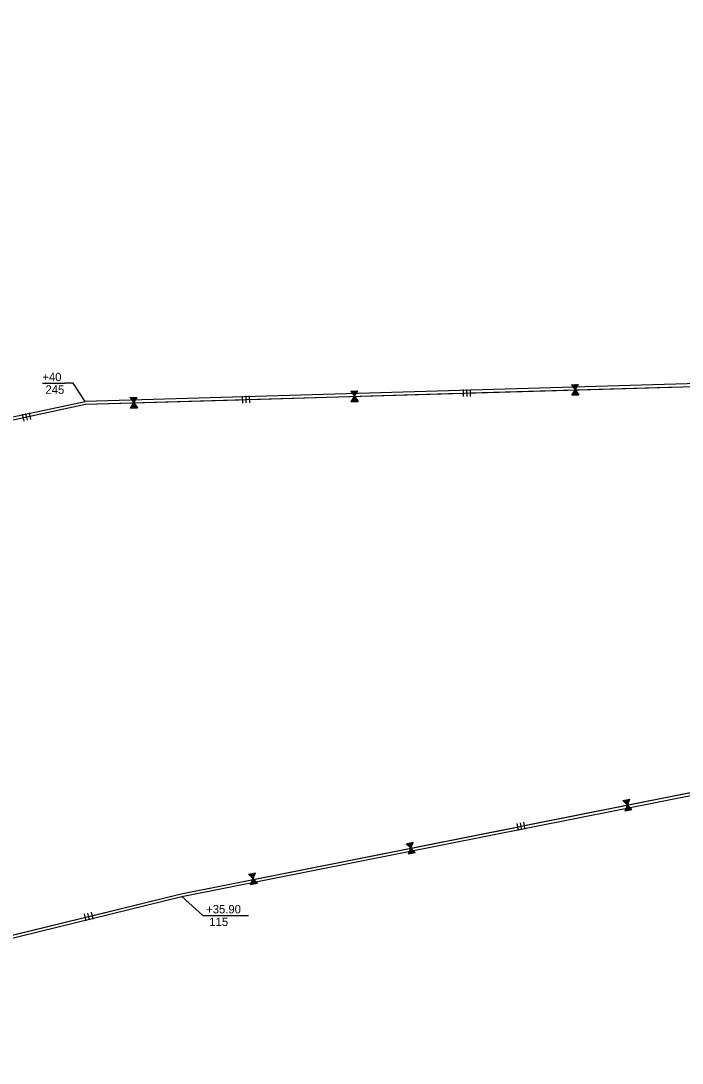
# Model space of a CAD drawing. Extents: x 979729 to 993523, y 1834148 to 1845433.
# Drawn here: x 985045 to 985517, y 1837649 to 1838393 of the extents above; entities that cross this region are included whole.
import ezdxf

# ---------------------------------------------------------------- set-up
doc = ezdxf.new("R2010")
doc.units = 0
for name, color, linetype in [('42', 7, 'Continuous'), ('51', 7, 'Continuous'), ('R_Draft', 7, 'Continuous')]:
    doc.layers.add(name, color=color, linetype=linetype)

msp = doc.modelspace()

# ---------------------------------------------------------------- linework, layer by layer
at = {"layer": '42'}
for p, q in [((985091.38, 1838119.28), (985811.99, 1838140.41)), ((985280.52, 1838128.58), (985283.13, 1838124.9)), ((985280.58, 1838128.52), (985280.62, 1838128.58)), ((985280.75, 1838128.32), (985280.92, 1838128.59)), ((985280.9, 1838128.08), (985281.22, 1838128.6)), ((985281.07, 1838127.88), (985281.52, 1838128.6)), ((985281.21, 1838127.64), (985281.82, 1838128.61)), ((985281.36, 1838127.4), (985282.12, 1838128.62)), ((985281.52, 1838127.2), (985282.42, 1838128.63)), ((985281.73, 1838127.05), (985282.63, 1838128.5)), ((985281.85, 1838126.78), (985283.02, 1838128.65)), ((985282.02, 1838126.58), (985283.32, 1838128.66)), ((985282.15, 1838126.32), (985283.62, 1838128.67)), ((985282.33, 1838126.14), (985283.92, 1838128.67)), ((985282.47, 1838125.87), (985284.22, 1838128.68)), ((985282.63, 1838125.67), (985284.52, 1838128.69)), ((985282.78, 1838125.43), (985284.82, 1838128.7)), ((985282.96, 1838125.25), (985285.12, 1838128.71)), ((985283.09, 1838124.99), (985285.42, 1838128.72)), ((985283.13, 1838124.9), (985285.52, 1838128.72)), ((985360.53, 1838129.67), (985360.67, 1838124.67)), ((985363.03, 1838129.74), (985363.17, 1838124.75)), ((985365.52, 1838129.82), (985365.67, 1838124.82)), ((985437.96, 1838133.19), (985440.57, 1838129.52)), ((985438.02, 1838133.14), (985438.05, 1838133.19)), ((985438.18, 1838132.94), (985438.35, 1838133.2)), ((985438.18, 1838125.69), (985440.57, 1838129.52)), ((985438.33, 1838132.7), (985438.65, 1838133.21)), ((985438.5, 1838132.49), (985438.95, 1838133.22)), ((985438.64, 1838132.26), (985439.25, 1838133.23)), ((985438.79, 1838132.02), (985439.55, 1838133.24)), ((985438.96, 1838131.81), (985439.85, 1838133.25)), ((985439.16, 1838131.67), (985440.06, 1838133.11)), ((985439.28, 1838131.4), (985440.45, 1838133.26)), ((985439.4, 1838127.56), (985440.67, 1838125.77)), ((985439.45, 1838131.19), (985440.75, 1838133.27)), ((985439.55, 1838127.78), (985440.97, 1838125.78)), ((985439.58, 1838130.93), (985441.05, 1838133.28)), ((985439.67, 1838128.05), (985441.27, 1838125.79)), ((985439.77, 1838130.75), (985441.35, 1838133.29)), ((985439.84, 1838128.24), (985441.57, 1838125.79)), ((985439.9, 1838130.49), (985441.65, 1838133.3)), ((985439.96, 1838128.5), (985441.87, 1838125.8)), ((985440.06, 1838130.29), (985441.95, 1838133.31)), ((985440.11, 1838128.72), (985442.17, 1838125.81)), ((985440.21, 1838130.05), (985442.25, 1838133.32)), ((985440.24, 1838128.96), (985442.47, 1838125.82)), ((985440.39, 1838129.87), (985442.55, 1838133.33)), ((985440.41, 1838129.15), (985442.77, 1838125.83)), ((985440.52, 1838129.61), (985442.85, 1838133.33)), ((985440.53, 1838129.42), (985443.07, 1838125.84)), ((985440.57, 1838129.52), (985442.95, 1838133.34)), ((985440.57, 1838129.52), (985443.17, 1838125.84)), ((985123.09, 1838123.96), (985125.7, 1838120.28)), ((985123.15, 1838123.91), (985123.19, 1838123.96)), ((985123.31, 1838116.46), (985125.7, 1838120.28)), ((985123.32, 1838123.7), (985123.49, 1838123.97)), ((985123.46, 1838123.47), (985123.79, 1838123.98)), ((985123.63, 1838123.26), (985124.09, 1838123.99)), ((985123.78, 1838123.02), (985124.39, 1838124)), ((985123.92, 1838122.79), (985124.69, 1838124.01)), ((985124.09, 1838122.58), (985124.99, 1838124.01)), ((985124.29, 1838122.43), (985125.2, 1838123.88)), ((985124.42, 1838122.16), (985125.59, 1838124.03)), ((985124.59, 1838121.96), (985125.89, 1838124.04)), ((985124.72, 1838121.7), (985126.19, 1838124.05)), ((985124.9, 1838121.52), (985126.49, 1838124.06)), ((985125.03, 1838121.26), (985126.79, 1838124.07)), ((985125.2, 1838121.06), (985127.09, 1838124.08)), ((985125.35, 1838120.82), (985127.39, 1838124.09)), ((985125.53, 1838120.64), (985127.69, 1838124.09)), ((985125.55, 1838119.92), (985127.91, 1838116.6)), ((985125.66, 1838120.38), (985127.99, 1838124.1)), ((985125.67, 1838120.19), (985128.21, 1838116.61)), ((985125.7, 1838120.28), (985128.09, 1838124.11)), ((985125.7, 1838120.28), (985128.31, 1838116.61)), ((985203.09, 1838125.05), (985203.24, 1838120.06)), ((985205.59, 1838125.13), (985205.74, 1838120.13)), ((985208.09, 1838125.2), (985208.24, 1838120.2)), ((985280.74, 1838121.08), (985283.13, 1838124.9)), ((985280.8, 1838121.14), (985280.84, 1838121.08)), ((985280.96, 1838121.35), (985281.14, 1838121.09)), ((985281.09, 1838121.59), (985281.44, 1838121.1)), ((985281.24, 1838121.81), (985281.74, 1838121.11)), ((985281.37, 1838122.05), (985282.04, 1838121.12)), ((985281.51, 1838122.3), (985282.34, 1838121.13)), ((985281.66, 1838122.51), (985282.64, 1838121.13)), ((985281.85, 1838122.67), (985282.84, 1838121.28)), ((985281.96, 1838122.95), (985283.24, 1838121.15)), ((985282.12, 1838123.16), (985283.54, 1838121.16)), ((985282.24, 1838123.43), (985283.84, 1838121.17)), ((985282.41, 1838123.62), (985284.14, 1838121.18)), ((985282.52, 1838123.89), (985284.44, 1838121.19)), ((985282.68, 1838124.1), (985284.74, 1838121.2)), ((985282.81, 1838124.35), (985285.04, 1838121.2)), ((985282.98, 1838124.54), (985285.34, 1838121.21)), ((985283.1, 1838124.81), (985285.64, 1838121.22)), ((985283.13, 1838124.9), (985285.74, 1838121.23)), ((985438.23, 1838125.75), (985438.27, 1838125.7)), ((985438.39, 1838125.96), (985438.57, 1838125.71)), ((985438.52, 1838126.21), (985438.87, 1838125.71)), ((985438.68, 1838126.42), (985439.17, 1838125.72)), ((985438.81, 1838126.67), (985439.47, 1838125.73)), ((985438.94, 1838126.91), (985439.77, 1838125.74)), ((985439.09, 1838127.13), (985440.07, 1838125.75)), ((985439.29, 1838127.29), (985440.28, 1838125.89)), ((985008.43, 1838101.52), (985091.38, 1838119.28)), ((985048.65, 1838112.69), (985049.7, 1838107.8)), ((985051.09, 1838113.21), (985052.14, 1838108.32)), ((985123.37, 1838116.52), (985123.4, 1838116.47)), ((985123.52, 1838116.73), (985123.71, 1838116.47)), ((985123.65, 1838116.98), (985124.01, 1838116.48)), ((985123.81, 1838117.19), (985124.31, 1838116.49)), ((985123.94, 1838117.44), (985124.61, 1838116.5)), ((985124.07, 1838117.68), (985124.91, 1838116.51)), ((985124.23, 1838117.9), (985125.21, 1838116.52)), ((985124.42, 1838118.06), (985125.41, 1838116.66)), ((985124.53, 1838118.33), (985125.81, 1838116.54)), ((985124.69, 1838118.54), (985126.11, 1838116.54)), ((985124.8, 1838118.81), (985126.41, 1838116.55)), ((985124.98, 1838119), (985126.71, 1838116.56)), ((985125.09, 1838119.27), (985127.01, 1838116.57)), ((985125.25, 1838119.49), (985127.31, 1838116.58)), ((985125.38, 1838119.73), (985127.61, 1838116.59)), ((985046.2, 1838112.16), (985047.25, 1838107.27)), ((985159.48, 1837769.83), (985982.51, 1837933.54)), ((985477.52, 1837833.46), (985479.07, 1837837.23)), ((985477.69, 1837833.22), (985479.37, 1837837.28)), ((985477.74, 1837833.14), (985479.46, 1837837.3)), ((985474.56, 1837836.33), (985477.74, 1837833.14)), ((985474.63, 1837836.29), (985474.65, 1837836.35)), ((985474.83, 1837836.11), (985474.95, 1837836.4)), ((985475.01, 1837835.9), (985475.24, 1837836.46)), ((985475.21, 1837835.73), (985475.54, 1837836.52)), ((985475.39, 1837835.52), (985475.83, 1837836.58)), ((985475.58, 1837835.31), (985476.13, 1837836.64)), ((985475.78, 1837835.14), (985476.42, 1837836.7)), ((985476, 1837835.02), (985476.65, 1837836.6)), ((985476.02, 1837828.97), (985477.74, 1837833.14)), ((985476.17, 1837834.78), (985477.01, 1837836.81)), ((985476.37, 1837834.61), (985477.3, 1837836.87)), ((985476.39, 1837829.77), (985477, 1837829.17)), ((985476.48, 1837830.04), (985477.29, 1837829.22)), ((985476.54, 1837834.37), (985477.6, 1837836.93)), ((985476.57, 1837830.3), (985477.59, 1837829.28)), ((985476.69, 1837830.54), (985477.88, 1837829.34)), ((985476.75, 1837834.22), (985477.89, 1837836.99)), ((985476.85, 1837830.73), (985478.06, 1837829.52)), ((985476.92, 1837833.99), (985478.19, 1837837.05)), ((985476.92, 1837831.02), (985478.47, 1837829.46)), ((985477.03, 1837831.25), (985478.77, 1837829.52)), ((985477.1, 1837831.54), (985479.06, 1837829.58)), ((985477.12, 1837833.82), (985478.48, 1837837.11)), ((985477.24, 1837831.76), (985479.36, 1837829.63)), ((985477.31, 1837833.6), (985478.78, 1837837.17)), ((985477.31, 1837832.04), (985479.65, 1837829.69)), ((985477.43, 1837832.27), (985479.95, 1837829.75)), ((985477.52, 1837832.54), (985480.24, 1837829.81)), ((985477.65, 1837832.75), (985480.54, 1837829.87)), ((985477.72, 1837833.04), (985480.83, 1837829.93)), ((985477.74, 1837833.14), (985480.93, 1837829.95)), ((985476.07, 1837829.04), (985476.11, 1837828.99)), ((985476.19, 1837829.27), (985476.41, 1837829.05)), ((985476.28, 1837829.54), (985476.7, 1837829.11)), ((985398.79, 1837819.98), (985399.77, 1837815.08)), ((985401.25, 1837820.47), (985402.22, 1837815.57)), ((985403.7, 1837820.96), (985404.67, 1837816.05)), ((985320.09, 1837805.6), (985323.27, 1837802.41)), ((985320.15, 1837805.56), (985320.18, 1837805.62)), ((985320.35, 1837805.39), (985320.47, 1837805.68)), ((985320.54, 1837805.18), (985320.77, 1837805.74)), ((985320.74, 1837805), (985321.06, 1837805.8)), ((985320.92, 1837804.79), (985321.36, 1837805.85)), ((985321.1, 1837804.58), (985321.65, 1837805.91)), ((985321.3, 1837804.41), (985321.95, 1837805.97)), ((985321.52, 1837804.3), (985322.18, 1837805.88)), ((985321.55, 1837798.25), (985323.27, 1837802.41)), ((985321.69, 1837804.05), (985322.54, 1837806.09)), ((985321.89, 1837803.88), (985322.83, 1837806.15)), ((985322.07, 1837803.64), (985323.13, 1837806.21)), ((985322.28, 1837803.5), (985323.42, 1837806.26)), ((985322.38, 1837800), (985323.59, 1837798.79)), ((985322.44, 1837800.29), (985324, 1837798.73)), ((985322.45, 1837803.26), (985323.71, 1837806.32)), ((985322.56, 1837800.53), (985324.29, 1837798.79)), ((985322.63, 1837800.81), (985324.59, 1837798.85)), ((985322.65, 1837803.09), (985324.01, 1837806.38)), ((985322.77, 1837801.03), (985324.88, 1837798.91)), ((985322.83, 1837802.88), (985324.3, 1837806.44)), ((985322.84, 1837801.31), (985325.18, 1837798.97)), ((985322.95, 1837801.55), (985325.47, 1837799.03)), ((985323.04, 1837802.73), (985324.6, 1837806.5)), ((985323.04, 1837801.81), (985325.77, 1837799.08)), ((985323.18, 1837802.03), (985326.06, 1837799.14)), ((985323.21, 1837802.49), (985324.89, 1837806.56)), ((985323.25, 1837802.31), (985326.36, 1837799.2)), ((985323.27, 1837802.41), (985324.99, 1837806.58)), ((985323.27, 1837802.41), (985326.45, 1837799.22)), ((985321.6, 1837798.31), (985321.64, 1837798.26)), ((985321.71, 1837798.55), (985321.94, 1837798.32)), ((985321.8, 1837798.81), (985322.23, 1837798.38)), ((985321.92, 1837799.05), (985322.53, 1837798.44)), ((985322.01, 1837799.31), (985322.82, 1837798.5)), ((985322.1, 1837799.57), (985323.12, 1837798.56)), ((985322.22, 1837799.81), (985323.41, 1837798.61)), ((985207.6, 1837783.84), (985210.78, 1837780.65)), ((985207.67, 1837783.8), (985207.69, 1837783.86)), ((985207.86, 1837783.62), (985207.99, 1837783.92)), ((985208.05, 1837783.41), (985208.28, 1837783.97)), ((985208.25, 1837783.24), (985208.57, 1837784.03)), ((985208.43, 1837783.03), (985208.87, 1837784.09)), ((985208.62, 1837782.82), (985209.16, 1837784.15)), ((985208.81, 1837782.65), (985209.46, 1837784.21)), ((985209.04, 1837782.53), (985209.69, 1837784.11)), ((985209.06, 1837776.48), (985210.78, 1837780.65)), ((985209.21, 1837782.29), (985210.05, 1837784.33)), ((985209.41, 1837782.12), (985210.34, 1837784.38)), ((985209.58, 1837781.88), (985210.64, 1837784.44)), ((985209.61, 1837777.81), (985210.63, 1837776.79)), ((985209.73, 1837778.05), (985210.92, 1837776.85)), ((985209.79, 1837781.73), (985210.93, 1837784.5)), ((985209.89, 1837778.24), (985211.1, 1837777.03)), ((985209.96, 1837781.5), (985211.23, 1837784.56)), ((985209.96, 1837778.53), (985211.51, 1837776.97)), ((985210.07, 1837778.76), (985211.81, 1837777.03)), ((985210.14, 1837779.05), (985212.1, 1837777.09)), ((985210.16, 1837781.33), (985211.52, 1837784.62)), ((985210.28, 1837779.27), (985212.4, 1837777.15)), ((985210.34, 1837781.11), (985211.82, 1837784.68)), ((985210.35, 1837779.55), (985212.69, 1837777.2)), ((985210.47, 1837779.78), (985212.98, 1837777.26)), ((985210.55, 1837780.97), (985212.11, 1837784.74)), ((985210.56, 1837780.05), (985213.28, 1837777.32)), ((985210.69, 1837780.27), (985213.57, 1837777.38)), ((985210.73, 1837780.73), (985212.4, 1837784.79)), ((985210.76, 1837780.55), (985213.87, 1837777.44)), ((985210.78, 1837780.65), (985212.5, 1837784.81)), ((985210.78, 1837780.65), (985213.97, 1837777.46)), ((985209.11, 1837776.55), (985209.15, 1837776.5)), ((985209.23, 1837776.78), (985209.45, 1837776.56)), ((985209.31, 1837777.05), (985209.74, 1837776.62)), ((985209.43, 1837777.28), (985210.04, 1837776.68)), ((985209.52, 1837777.55), (985210.33, 1837776.73)), ((984764.91, 1837673.05), (985159.48, 1837769.83)), ((985090.41, 1837755.47), (985091.6, 1837750.61)), ((985092.84, 1837756.06), (985094.03, 1837751.2)), ((985095.27, 1837756.66), (985096.46, 1837751.8))]:
    msp.add_line(p, q, dxfattribs=at)
for points in [[(985280.52, 1838128.58), (985285.52, 1838128.72)], [(985365.6, 1838127.32), (985515.53, 1838131.71)], [(985437.96, 1838133.19), (985442.95, 1838133.34)], [(985051.62, 1838110.77), (985091.38, 1838119.28), (985200.67, 1838122.48)], [(985123.09, 1838123.96), (985128.09, 1838124.11)], [(985208.17, 1838122.7), (985358.1, 1838127.1)], [(985280.74, 1838121.08), (985285.74, 1838121.23)], [(985438.18, 1838125.69), (985443.17, 1838125.84)], [(985123.31, 1838116.46), (985128.31, 1838116.61)], [(985404.19, 1837818.51), (985551.3, 1837847.77)], [(985474.56, 1837836.33), (985479.46, 1837837.3)], [(985476.02, 1837828.97), (985480.93, 1837829.95)], [(985159.48, 1837769.83), (985396.83, 1837817.04)], [(985320.09, 1837805.6), (985324.99, 1837806.58)], [(985321.55, 1837798.25), (985326.45, 1837799.22)], [(985207.6, 1837783.84), (985212.5, 1837784.81)], [(985209.06, 1837776.48), (985213.97, 1837777.46)], [(985095.86, 1837754.23), (985159.48, 1837769.83)], [(984954.54, 1837719.57), (985088.58, 1837752.44)]]:
    msp.add_lwpolyline(points, dxfattribs=at)
at = {"layer": '51'}
msp.add_line((985159.91, 1837767.88), (986515.41, 1838037.5), dxfattribs=at)
for points in [[(983839.63, 1837883.59), (983964.23, 1837883.62), (984287.23, 1838143), (984453.05, 1838392.87), (984546.56, 1838335.6), (984387.83, 1838097.74), (984180.84, 1837884.6), (984295.61, 1837882.99), (984364.62, 1837995.97), (984581.88, 1838016.14), (985008.02, 1838103.48), (985091.14, 1838121.27)], [(986526.26, 1838289.91), (985811.75, 1838142.4), (985091.14, 1838121.27)], [(983832.14, 1837610.35), (983899.28, 1837624.99), (983877.1, 1837385.75), (983914.53, 1837124.26), (983905.65, 1836909.01), (984013.18, 1836905.08), (984017.58, 1837080.16), (984054.32, 1837258.25), (984179.74, 1837534.6), (984311.6, 1837538.33), (984765.43, 1837671.12), (985159.91, 1837767.88)]]:
    msp.add_lwpolyline(points, dxfattribs=at)
at = {"layer": 'R_Draft'}
for p, q in [((985060.68, 1838134.21), (985076.48, 1838134.21)), ((985181.02, 1837754.36), (985207.6, 1837754.36))]:
    msp.add_line(p, q, dxfattribs=at)
for points in [[(985091.14, 1838121.27), (985082.48, 1838134.21), (985076.48, 1838134.21)], [(985159.91, 1837767.88), (985175.02, 1837754.36), (985181.02, 1837754.36)]]:
    msp.add_lwpolyline(points, dxfattribs=at)

# ---------------------------------------------------------------- texts
for s, p in [('+40', (985060.57, 1838135.71)), (' 245', (985060.57, 1838126.71)), ('+35.90', (985177.39, 1837755.86)), (' 115', (985177.39, 1837746.86))]:
    msp.add_text(s, height=6, rotation=360, dxfattribs=at).set_placement(p)

doc.saveas('drawing.dxf')
